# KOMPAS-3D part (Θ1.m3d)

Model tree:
1. Эскиз:1
2. Операция выдавливания:1
     Расстояние 1 = 2
3. Скругление:1
     Радиус = 2
4. Скругление:2
     Радиус = 2
5. Эскиз:2
6. Вырезать элемент выдавливания:1
     Расстояние 1 = 10
